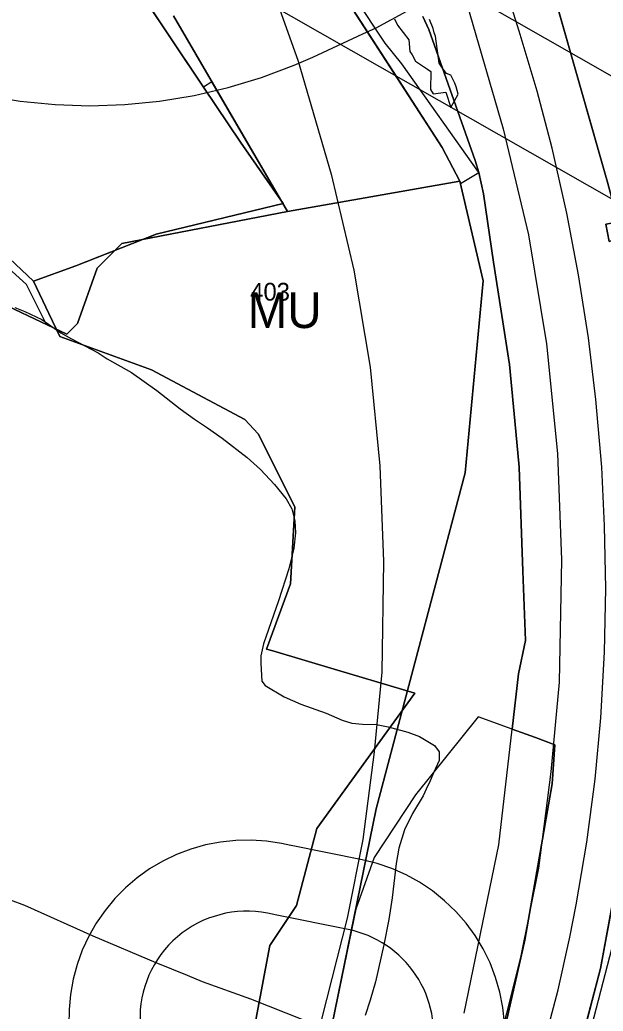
# Model space of a CAD drawing. Extents: x -690419 to -685080, y -987825 to -981190.
# Drawn here: x -686831.2 to -686667.2, y -986534.9 to -986256.1 of the extents above; entities that cross this region are included whole.
import ezdxf

# ---------------------------------------------------------------- set-up
doc = ezdxf.new("R2010")
doc.units = 0
for name, color, linetype in [('BP VTL plynovodu a RS (S)', 7, 'Continuous'), ('BPEJ (S) - hranice', 7, 'Continuous'), ('BPEJ I-II ochrana', 7, 'Continuous'), ('Elektro VVN 220 nadzemni (S)', 7, 'Continuous'), ('Katastrální území (S) - hranice', 7, 'Continuous'), ('OP elektro VN (S)', 7, 'Continuous'), ('OP lesa 30 m (S)', 7, 'Continuous'), ('OP lesa 50 m (S)', 7, 'Continuous'), ('OP silnic (S)', 7, 'Continuous'), ('OP ČOV (S)', 7, 'Continuous'), ('Plochy dopravy silniční DS (S)', 7, 'Continuous'), ('Plochy smíšené nezastavěného území všeobecné MU (S)', 7, 'Continuous'), ('Plochy zemědělské všeobecné AU (S)', 7, 'Continuous'), ('Regulacni bloky_ID', 7, 'Continuous'), ('Regulační bloky STABILIZOVANÉ (S)', 7, 'Continuous'), ('Regulační kódy STABILIZOVANÉ (S)', 7, 'Continuous'), ('Silnice I třídy (S) - osa', 7, 'Continuous'), ('Spoje - optický komunikační kabel (S)', 7, 'Continuous'), ('Záplavové území Q100 (S)', 7, 'Continuous')]:
    doc.layers.add(name, color=color, linetype=linetype)

msp = doc.modelspace()

# ---------------------------------------------------------------- linework, layer by layer
at = {"layer": 'BP VTL plynovodu a RS (S)'}
msp.add_lwpolyline([(-686718.44, -986551.27), (-686719.78, -986550.69), (-686720.39, -986550.43), (-686720.43, -986550.41), (-686721.07, -986550.14), (-686728.72, -986546.38), (-686751.35, -986537.48), (-686766.24, -986531.61), (-686779.85, -986526.72), (-686784.04, -986524.91), (-686792.89, -986521.35), (-686810.58, -986513.88), (-686829.79, -986505.2), (-686833.81, -986503.77)], dxfattribs=at)
at = {"layer": 'BPEJ (S) - hranice'}
for points in [[(-686936.25, -987205.68), (-686932.5, -987151.5), (-686895.96, -987000), (-686884.5, -986953.5), (-686813.5, -986784), (-686759.5, -986617.5), (-686731, -986478), (-686706, -986383.5), (-686701, -986329.5), (-686707.5, -986301.5), (-686712.5, -986292), (-686755.5, -986225.5)], [(-686755.5, -986225.5), (-686712.5, -986292), (-686707.5, -986301.5), (-686756, -986310), (-686788, -986255)], [(-686788, -986255), (-686756, -986310), (-686802.5, -986319), (-686809.5, -986326), (-686815, -986341.5), (-686818, -986344.5), (-686865.5, -986322)], [(-686865.5, -986322), (-686818, -986344.5), (-686815, -986341.5), (-686809.5, -986326), (-686802.5, -986319), (-686756, -986310), (-686707.5, -986301.5), (-686701, -986329.5), (-686706, -986383.5), (-686731, -986478), (-686759.5, -986617.5), (-686813.5, -986784), (-686884.5, -986953.5)]]:
    msp.add_lwpolyline(points, dxfattribs=at)
at = {"layer": 'BPEJ I-II ochrana'}
for p, q in [((-686779.54, -986275.03), (-686800.79, -986243.34)), ((-686728.51, -986262.74), (-686737.9, -986248.45)), ((-686739.85, -986249.7), (-686726.49, -986270.37)), ((-686723.81, -986268.48), (-686728.51, -986262.74)), ((-686702.2, -986299.07), (-686723.81, -986268.48)), ((-686777.21, -986273.54), (-686779.54, -986275.03)), ((-686767.66, -986289.97), (-686777.21, -986273.54)), ((-686757.77, -986306.96), (-686767.66, -986289.97)), ((-686707.35, -986302.14), (-686702.2, -986299.07)), ((-686757.28, -986307.8), (-686757.77, -986306.96)), ((-686792.86, -986316.45), (-686757.28, -986307.8)), ((-686840.43, -986317.31), (-686827.37, -986329.65)), ((-686796.29, -986317.8), (-686792.86, -986316.45)), ((-686829.39, -986330.54), (-686841.8, -986319.33)), ((-686815.51, -986325.35), (-686804.54, -986321.04)), ((-686827.37, -986329.65), (-686815.51, -986325.35)), ((-686823.74, -986341.78), (-686829.39, -986330.54)), ((-686702.4, -986452.18), (-686720.01, -986474.07)), ((-686692.82, -986455.65), (-686702.4, -986452.18)), ((-686696.51, -986488.17), (-686692.82, -986455.65)), ((-686720.01, -986474.07), (-686731.64, -986491.77)), ((-686659.13, -986474.94), (-686667.92, -986522.94)), ((-686706.34, -986535.51), (-686696.51, -986488.17)), ((-686731.64, -986491.77), (-686736.78, -986506.3)), ((-686736.78, -986506.3), (-686743.98, -986541.55)), ((-686667.92, -986522.94), (-686676.51, -986555.42))]:
    msp.add_line(p, q, dxfattribs=at)
for points in [[(-686726.49, -986270.37), (-686712.5, -986292), (-686707.5, -986301.5), (-686707.35, -986302.14)], [(-686891.93, -986316.97), (-686886.5, -986314.5), (-686865.5, -986322), (-686823.74, -986341.78)], [(-686804.54, -986321.04), (-686802.5, -986319), (-686796.29, -986317.8)]]:
    msp.add_lwpolyline(points, dxfattribs=at)
at = {"layer": 'Elektro VVN 220 nadzemni (S)'}
msp.add_lwpolyline([(-686883.06, -986147.5), (-686512.82, -986358.6)], dxfattribs=at)
at = {"layer": 'Katastrální území (S) - hranice'}
for points in [[(-686689.98, -986217.58), (-686665.99, -986301.77), (-686664.4, -986307.82), (-686663.83, -986313.14), (-686666.51, -986313.61), (-686665.56, -986318.5), (-686663.33, -986317.82), (-686662.66, -986324.04), (-686657.08, -986369.79), (-686655.33, -986417.82), (-686658.73, -986468.88), (-686659.13, -986474.94), (-686667.92, -986522.94), (-686676.51, -986555.42), (-686679.91, -986568.27), (-686701.4, -986629.61), (-686711.68, -986654.16), (-686719.78, -986673.5), (-686721.14, -986676.76), (-686721.61, -986676.58), (-686723.39, -986681.23), (-686722.93, -986681.41), (-686724.72, -986686.27), (-686745.98, -986743.92)], [(-686745.98, -986743.92), (-686724.72, -986686.27), (-686722.93, -986681.41), (-686723.39, -986681.23), (-686721.61, -986676.58), (-686721.14, -986676.76), (-686719.78, -986673.5), (-686711.68, -986654.16), (-686701.4, -986629.61), (-686679.91, -986568.27), (-686676.51, -986555.42), (-686667.92, -986522.94), (-686659.13, -986474.94), (-686658.73, -986468.88), (-686655.33, -986417.82), (-686657.08, -986369.79), (-686662.66, -986324.04), (-686663.33, -986317.82), (-686665.56, -986318.5), (-686666.51, -986313.61), (-686663.83, -986313.14), (-686664.4, -986307.82), (-686665.99, -986301.77), (-686689.98, -986217.58)]]:
    msp.add_lwpolyline(points, dxfattribs=at)
at = {"layer": 'OP elektro VN (S)'}
msp.add_lwpolyline([(-686717.27, -986722.57), (-686879.05, -986537.04), (-687014.87, -986381.01), (-687207.62, -986159.36), (-687403.95, -985933.85), (-687488.97, -985836.27), (-687337.77, -985922.59), (-686897.92, -986173.56), (-686637.5, -986322.05), (-686649.13, -986456.85), (-686684.89, -986594.79), (-686717.27, -986722.57)], close=True, dxfattribs=at)
at = {"layer": 'OP lesa 30 m (S)'}
for p, q in [((-686758.96, -986507.94), (-686761.56, -986507.42)), ((-686738.94, -986511.97), (-686758.93, -986507.95))]:
    msp.add_line(p, q, dxfattribs=at)
for centre, start, end in [((-686767.44, -986536.84), 78.6901, 182.2556), ((-686764.84, -986537.36), 78.6294, 78.6901), ((-686744.85, -986541.38), 348.5583, 78.6294)]:
    msp.add_arc(centre, 30, start, end, dxfattribs=at)
at = {"layer": 'OP lesa 50 m (S)'}
msp.add_lwpolyline([(-686694.95, -986538.27), (-686695.41, -986533.93), (-686696.25, -986529.64), (-686697.46, -986525.45), (-686699.03, -986521.37), (-686700.95, -986517.45), (-686703.2, -986513.71), (-686705.77, -986510.19), (-686708.64, -986506.9), (-686711.79, -986503.87), (-686715.19, -986501.13), (-686718.81, -986498.7), (-686722.63, -986496.59), (-686726.62, -986494.82), (-686730.75, -986493.41), (-686734.99, -986492.36), (-686754.98, -986488.34), (-686755.03, -986488.33), (-686757.63, -986487.81), (-686761.89, -986487.15), (-686766.18, -986486.86), (-686770.48, -986486.93), (-686774.76, -986487.38), (-686778.98, -986488.19), (-686783.12, -986489.36), (-686787.15, -986490.89), (-686791.03, -986492.75), (-686794.73, -986494.94), (-686798.23, -986497.44), (-686801.5, -986500.24), (-686804.52, -986503.3), (-686807.27, -986506.61), (-686809.72, -986510.15), (-686811.86, -986513.88), (-686813.67, -986517.78), (-686815.13, -986521.83), (-686816.25, -986525.98), (-686817, -986530.22), (-686817.39, -986534.51), (-686817.4, -986538.81)], dxfattribs=at)
at = {"layer": 'OP silnic (S)'}
msp.add_lwpolyline([(-686770.45, -986218.55), (-686752.96, -986267.72), (-686743.7, -986299.55), (-686737.27, -986326.53), (-686732.73, -986353.86), (-686729.97, -986381.55), (-686728.94, -986408.48), (-686729.49, -986439.6), (-686731.6, -986462.05), (-686734.79, -986486.63), (-686739.21, -986508.83), (-686746.39, -986537.2), (-686755.51, -986566.52), (-686766.32, -986596.72), (-686817.81, -986728.15), (-686854.98, -986826.72), (-686855.91, -986829.4), (-686880.1, -986906.53), (-686880.96, -986909.61), (-686900.81, -986990.65), (-686918.72, -987067.01), (-686954.7, -987219.72)], dxfattribs=at)
at = {"layer": 'OP ČOV (S)'}
msp.add_lwpolyline([(-686894.85, -986255.01), (-686886.51, -986260.2), (-686877.86, -986264.82), (-686868.92, -986268.88), (-686859.73, -986272.33), (-686850.34, -986275.18), (-686840.78, -986277.41), (-686831.09, -986279.01), (-686821.32, -986279.97), (-686811.51, -986280.29), (-686801.7, -986279.97), (-686791.93, -986279.01), (-686782.25, -986277.41), (-686772.69, -986275.18), (-686763.3, -986272.33), (-686754.11, -986268.88), (-686748.89, -986266.6), (-686734.79, -986260.12), (-686731.07, -986258.35), (-686722.42, -986253.72)], dxfattribs=at)
at = {"layer": 'Plochy dopravy silniční DS (S)'}
for p, q in [((-686689.98, -986217.58), (-686665.99, -986301.77)), ((-686716.22, -986258.82), (-686717.93, -986255.2)), ((-686703.16, -986295.66), (-686716.22, -986258.82)), ((-686702.2, -986299.07), (-686703.16, -986295.66)), ((-686700.9, -986305.11), (-686702.2, -986299.07)), ((-686698.07, -986324.34), (-686700.9, -986305.11)), ((-686693.57, -986353.07), (-686698.07, -986324.34)), ((-686691.77, -986371.94), (-686693.57, -986353.07)), ((-686690.81, -986381.94), (-686691.77, -986371.94)), ((-686689.78, -986411.16), (-686690.81, -986381.94)), ((-686689.02, -986430.68), (-686689.78, -986411.16)), ((-686691.05, -986440.1), (-686689.02, -986430.68)), ((-686692.82, -986455.65), (-686691.05, -986440.1)), ((-686686.25, -986458.02), (-686692.82, -986455.65)), ((-686680.77, -986460), (-686686.25, -986458.02)), ((-686681.6, -986470.97), (-686680.77, -986460)), ((-686689.24, -986514.99), (-686681.6, -986470.97)), ((-686659.13, -986474.94), (-686667.92, -986522.94)), ((-686695.89, -986544.36), (-686689.24, -986514.99)), ((-686667.92, -986522.94), (-686676.51, -986555.42))]:
    msp.add_line(p, q, dxfattribs=at)
at = {"layer": 'Plochy smíšené nezastavěného území všeobecné MU (S)'}
for points in [[(-686764.84, -986537.36), (-686760.96, -986516.48), (-686753.43, -986505.25), (-686747.75, -986483.59), (-686720.14, -986445.5), (-686741.89, -986439.01), (-686760.1, -986433.58), (-686761.86, -986433.13), (-686755.12, -986414.77), (-686753.86, -986393.15), (-686764.24, -986372.62), (-686767.99, -986368.53), (-686794.25, -986354.56), (-686819.99, -986345.22), (-686823.06, -986338.74), (-686827.37, -986329.65), (-686815.51, -986325.35), (-686792.86, -986316.45), (-686757.2, -986307.78), (-686769.16, -986290.55), (-686779.54, -986275.03), (-686800.79, -986243.34)], [(-686717.93, -986255.2), (-686716.22, -986258.82), (-686703.16, -986295.66), (-686702.2, -986299.07), (-686700.9, -986305.11), (-686698.07, -986324.34), (-686693.57, -986353.07), (-686691.77, -986371.94), (-686690.81, -986381.94), (-686689.78, -986411.16), (-686689.02, -986430.68), (-686691.05, -986440.1), (-686692.82, -986455.65), (-686686.25, -986458.02), (-686680.77, -986460), (-686681.6, -986470.97), (-686689.24, -986514.99), (-686695.89, -986544.36)]]:
    msp.add_lwpolyline(points, dxfattribs=at)
at = {"layer": 'Plochy zemědělské všeobecné AU (S)'}
msp.add_lwpolyline([(-686671.4, -986248.73), (-686644.68, -986241.46), (-686643.38, -986256.33), (-686632.23, -986279.81), (-686597.54, -986288.3), (-686596.93, -986298.95), (-686663.83, -986313.14), (-686664.4, -986307.82), (-686665.99, -986301.77), (-686689.98, -986217.58), (-686678.31, -986216.57)], close=True, dxfattribs=at)
for points in [[(-686800.79, -986243.34), (-686779.54, -986275.03), (-686769.16, -986290.55), (-686757.2, -986307.78), (-686792.86, -986316.45), (-686815.51, -986325.35), (-686827.37, -986329.65), (-686823.06, -986338.74), (-686819.99, -986345.22), (-686794.25, -986354.56), (-686767.99, -986368.53), (-686764.24, -986372.62), (-686753.86, -986393.15), (-686755.12, -986414.77), (-686761.86, -986433.13), (-686760.1, -986433.58), (-686741.89, -986439.01), (-686720.14, -986445.5), (-686747.75, -986483.59), (-686753.43, -986505.25), (-686760.96, -986516.48), (-686764.84, -986537.36)], [(-686676.51, -986555.42), (-686667.92, -986522.94), (-686659.13, -986474.94), (-686658.73, -986468.88), (-686655.33, -986417.82), (-686657.08, -986369.79), (-686662.66, -986324.04), (-686663.33, -986317.82), (-686596.08, -986305.34), (-686570.29, -986348.74), (-686562.52, -986391.3), (-686560.8, -986399.5), (-686557.38, -986401.84), (-686553.34, -986411.64), (-686558.79, -986434.27), (-686537.77, -986479.73), (-686538.55, -986540.3)]]:
    msp.add_lwpolyline(points, dxfattribs=at)
at = {"layer": 'Regulační bloky STABILIZOVANÉ (S)'}
for p, q in [((-686689.98, -986217.58), (-686665.99, -986301.77)), ((-686716.22, -986258.82), (-686717.93, -986255.2)), ((-686703.16, -986295.66), (-686716.22, -986258.82)), ((-686702.2, -986299.07), (-686703.16, -986295.66)), ((-686700.9, -986305.11), (-686702.2, -986299.07)), ((-686698.07, -986324.34), (-686700.9, -986305.11)), ((-686693.57, -986353.07), (-686698.07, -986324.34)), ((-686691.77, -986371.94), (-686693.57, -986353.07)), ((-686690.81, -986381.94), (-686691.77, -986371.94)), ((-686689.78, -986411.16), (-686690.81, -986381.94)), ((-686689.02, -986430.68), (-686689.78, -986411.16)), ((-686691.05, -986440.1), (-686689.02, -986430.68)), ((-686692.82, -986455.65), (-686691.05, -986440.1)), ((-686686.25, -986458.02), (-686692.82, -986455.65)), ((-686680.77, -986460), (-686686.25, -986458.02)), ((-686681.6, -986470.97), (-686680.77, -986460)), ((-686689.24, -986514.99), (-686681.6, -986470.97)), ((-686659.13, -986474.94), (-686667.92, -986522.94)), ((-686695.89, -986544.36), (-686689.24, -986514.99)), ((-686667.92, -986522.94), (-686676.51, -986555.42))]:
    msp.add_line(p, q, dxfattribs=at)
msp.add_lwpolyline([(-686671.4, -986248.73), (-686644.68, -986241.46), (-686643.38, -986256.33), (-686632.23, -986279.81), (-686597.54, -986288.3), (-686596.93, -986298.95), (-686663.83, -986313.14), (-686664.4, -986307.82), (-686665.99, -986301.77), (-686689.98, -986217.58), (-686678.31, -986216.57)], close=True, dxfattribs=at)
for points in [[(-686764.84, -986537.36), (-686760.96, -986516.48), (-686753.43, -986505.25), (-686747.75, -986483.59), (-686720.14, -986445.5), (-686741.89, -986439.01), (-686760.1, -986433.58), (-686761.86, -986433.13), (-686755.12, -986414.77), (-686753.86, -986393.15), (-686764.24, -986372.62), (-686767.99, -986368.53), (-686794.25, -986354.56), (-686819.99, -986345.22), (-686823.06, -986338.74), (-686827.37, -986329.65), (-686815.51, -986325.35), (-686792.86, -986316.45), (-686757.2, -986307.78), (-686769.16, -986290.55), (-686779.54, -986275.03), (-686800.79, -986243.34)], [(-686800.79, -986243.34), (-686779.54, -986275.03), (-686769.16, -986290.55), (-686757.2, -986307.78), (-686792.86, -986316.45), (-686815.51, -986325.35), (-686827.37, -986329.65), (-686823.06, -986338.74), (-686819.99, -986345.22), (-686794.25, -986354.56), (-686767.99, -986368.53), (-686764.24, -986372.62), (-686753.86, -986393.15), (-686755.12, -986414.77), (-686761.86, -986433.13), (-686760.1, -986433.58), (-686741.89, -986439.01), (-686720.14, -986445.5), (-686747.75, -986483.59), (-686753.43, -986505.25), (-686760.96, -986516.48), (-686764.84, -986537.36)], [(-686717.93, -986255.2), (-686716.22, -986258.82), (-686703.16, -986295.66), (-686702.2, -986299.07), (-686700.9, -986305.11), (-686698.07, -986324.34), (-686693.57, -986353.07), (-686691.77, -986371.94), (-686690.81, -986381.94), (-686689.78, -986411.16), (-686689.02, -986430.68), (-686691.05, -986440.1), (-686692.82, -986455.65), (-686686.25, -986458.02), (-686680.77, -986460), (-686681.6, -986470.97), (-686689.24, -986514.99), (-686695.89, -986544.36)], [(-686676.51, -986555.42), (-686667.92, -986522.94), (-686659.13, -986474.94), (-686658.73, -986468.88), (-686655.33, -986417.82), (-686657.08, -986369.79), (-686662.66, -986324.04), (-686663.33, -986317.82), (-686596.08, -986305.34), (-686570.29, -986348.74), (-686562.52, -986391.3), (-686560.8, -986399.5), (-686557.38, -986401.84), (-686553.34, -986411.64), (-686558.79, -986434.27), (-686537.77, -986479.73), (-686538.55, -986540.3)]]:
    msp.add_lwpolyline(points, dxfattribs=at)
at = {"layer": 'Silnice I třídy (S) - osa'}
for points in [[(-686681.99, -986537.14), (-686679.89, -986528.94), (-686676.6, -986514.13), (-686674.77, -986505), (-686671.83, -986487.38), (-686669.45, -986469.68), (-686667.86, -986452.45), (-686666.83, -986433.96), (-686666.44, -986416.1), (-686666.83, -986398.48), (-686667.63, -986381.97), (-686669.29, -986362.92), (-686671.36, -986345.53), (-686674.14, -986327.83), (-686677.47, -986310.53), (-686681.52, -986292.27), (-686685.8, -986276.16), (-686690.8, -986259.33), (-686696.04, -986242.5)], [(-686705.36, -986252.34), (-686695.34, -986286.77), (-686688.23, -986316.63), (-686683.14, -986347.28), (-686680.06, -986378.11), (-686678.92, -986407.97), (-686679.54, -986442.39), (-686681.91, -986467.6), (-686685.42, -986494.74), (-686690.43, -986519.86), (-686698.24, -986550.77), (-686708.08, -986582.39), (-686719.5, -986614.27), (-686771.14, -986746.09), (-686808.2, -986844.37), (-686832.4, -986921.5), (-686852.19, -987002.31), (-686870.04, -987078.45), (-686905.97, -987230.91)]]:
    msp.add_lwpolyline(points, dxfattribs=at)
at = {"layer": 'Spoje - optický komunikační kabel (S)'}
msp.add_lwpolyline([(-686832.67, -986337.06), (-686829.8, -986338.16), (-686825.06, -986340.46), (-686819.68, -986344.13), (-686816.67, -986345.89), (-686809.23, -986349.76), (-686806.63, -986351.45), (-686799.79, -986355.37), (-686792.68, -986360.36), (-686786.17, -986365.51), (-686782.08, -986368.44), (-686778.42, -986370.88), (-686774.32, -986373.79), (-686767.28, -986379.2), (-686763.55, -986382.64), (-686759.64, -986386.82), (-686756.32, -986390.89), (-686754.79, -986393.68), (-686753.88, -986397), (-686753.71, -986400.45), (-686754.21, -986404.76), (-686755.63, -986410.56), (-686758.46, -986419.56), (-686762.76, -986431.66), (-686763.45, -986435.01), (-686763.45, -986437.21), (-686763.22, -986442.1), (-686762.29, -986443.32), (-686756.86, -986446.53), (-686752.23, -986448.56), (-686745.1, -986451.1), (-686740.59, -986453.11), (-686737.9, -986453.91), (-686734.92, -986454.21), (-686730.92, -986454.34), (-686727.62, -986454.96), (-686722.11, -986456.48), (-686718.9, -986457.74), (-686714.67, -986460.26), (-686713.36, -986462.05), (-686713.3, -986464.45), (-686714.81, -986467.71), (-686716.18, -986470.85), (-686716.47, -986471.46), (-686717.8, -986474.36), (-686720.81, -986479.4), (-686723.11, -986483.9), (-686724.64, -986489.11), (-686725.41, -986493.39), (-686726.53, -986503.05), (-686727.45, -986509.13), (-686728.85, -986516.29), (-686731.19, -986526.66), (-686732.68, -986531.88), (-686734.15, -986536.18)], dxfattribs=at)
at = {"layer": 'Záplavové území Q100 (S)'}
msp.add_lwpolyline([(-686725.86, -986255.86), (-686725, -986257.63), (-686721.81, -986261.81), (-686721.6, -986265), (-686720.94, -986265.94), (-686720, -986267.81), (-686716.64, -986270), (-686715.63, -986270.63), (-686715.74, -986275.74), (-686715, -986276.95), (-686711.46, -986276.46), (-686710, -986280.8), (-686707.95, -986277.05), (-686708.58, -986275), (-686708.93, -986273.93), (-686710, -986271.71), (-686711.26, -986271.26), (-686712.16, -986270), (-686713.33, -986268.33), (-686714.31, -986260.69), (-686714.76, -986259.76), (-686715, -986258.62), (-686716.04, -986256.04)], dxfattribs=at)

# ---------------------------------------------------------------- texts
at = {"layer": 'Regulacni bloky_ID'}
msp.add_text('403', height=5, dxfattribs=at).set_placement((-686766.44, -986335.11))
at = {"layer": 'Regulační kódy STABILIZOVANÉ (S)'}
msp.add_text('MU', height=10, dxfattribs=at).set_placement((-686767.18, -986342.82))

doc.saveas('drawing.dxf')
